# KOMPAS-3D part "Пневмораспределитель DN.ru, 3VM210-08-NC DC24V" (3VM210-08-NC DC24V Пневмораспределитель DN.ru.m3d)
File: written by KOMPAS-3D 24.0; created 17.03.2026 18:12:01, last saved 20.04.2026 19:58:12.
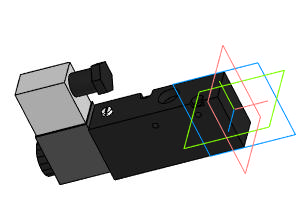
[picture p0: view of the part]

Document properties: Автор: R2D2; Полное имя файла: E:\Работа\Зайцев\Аксессуары для пневмоприводов\Пневмораспределители DN.ru\3VM210-08-NC Пневмораспределитель DN.RU\DC24V\3VM210-08-NC DC24V Пневмораспределитель DN.ru.m3d

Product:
- Part/product: Пневмораспределитель DN.ru  | designation 3VM210-08-NC DC24V
    Масса: 0.3
    Раздел спецификации: Прочие изделия
    Примечание: D290-00374

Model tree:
1. Операция без истории:1

Expressions: 3VM210-08-NC DC24V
